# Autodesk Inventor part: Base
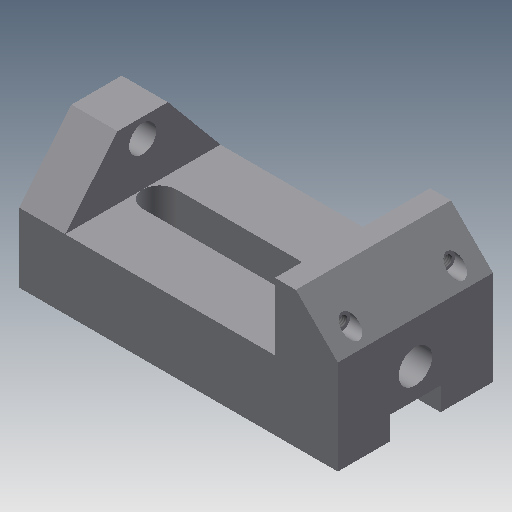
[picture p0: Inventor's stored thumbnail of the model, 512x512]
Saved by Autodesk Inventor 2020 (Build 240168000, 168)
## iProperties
Created: 2002-02
Part Number: Base
Document SubType Name: Modeling
Designer: ***
Density: 1 g/cm^3
Material: Generic
Appearance: Default
Control State: 0
Master: False
Checked Out: False
Shininess: 77.0
Length Units: 11269
Angle Units: 11279
Time Units: 11290
Mass Units: 11283
Length Display Precision: 3
Angle Display Precision: 2
Density: 0.0
Volumn: 0.0
Area: 0.0
PropertySet Name: Model Information
Author: ***
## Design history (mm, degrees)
sketch "Sketch2"
  geometry: L1 (-63.961, -4.254)-(-63.961, -37.254); L2 (-63.961, -37.254)-(88.039, -37.254); L3 (88.039, -37.254)-(88.039, 7.746); L4 (88.039, 7.746)-(68.039, 27.746); L5 (68.039, 27.746)-(58.039, 27.746); L6 (58.039, 27.746)-(58.039, -4.254); L7 (58.039, -4.254)-(-63.961, -4.254)
  constraints: 14 end point, 4 parallel, 1 perpendicular, 1 vertical
  dimensions: "d7" = 10 distance of L4.end L5.end; "d8" = 135 deg angle of L3 L4; "d9" = 33 distance of L1.start L1.end; "d10" = 152 distance of L1.end L2.end; "d11" = 65 distance between parallel lines of L5 L2; "d21" = 30 distance between parallel lines of L3 L6
extrude "Extrusion1" new body sketch "Sketch2" stored distance "d13" = 74; taper "d14" = 0 deg
sketch "Sketch3"
  geometry: L1 (0, 74)-(0, 0) reference; L2 (0, 0)-(-30, 25); L3 (-30, 25)-(-30, 49); L4 (-30, 49)-(0, 74); C1 r 6.5 at (-21, 37)
  constraints: 6 end point, 1 centre point, 1 equal length, 1 parallel
  dimensions: "d15" = 24 distance of L2.end L3.end; "d16" = 30 distance between parallel lines of L3 L1; "d17" = 13 diameter of C1; "d18" = 9 distance from line of L3 C1.centre
extrude "Extrusion2" join sketch "Sketch3" distance "d19" = 22; taper "d20" = 0 deg
sketch "Sketch4"
  geometry: L1 (0, 0)-(0, 74) reference; L2 (0, 0)-(45, 0) reference; C1 r 8 at (25, 37)
  constraints: 1 centre point
  dimensions: "d22" = 16 diameter of C1; "d23" = 25 distance from line of L1 C1.centre; "d24" = 37 distance from line of L2 C1.centre
extrude "Extrusion3" cut sketch "Sketch4" distance "d25" = 13; taper "d26" = 0 deg
sketch "Sketch5"
  geometry: L1 (45, 74)-(0, 74) reference; L2 (65, 0)-(65, 74) reference; 1 further point
  dimensions: "d27" = 12 distance from line of point (51, 62) L1; "d28" = 14 distance from line of L2 point (51, 62)
hole "Hole1" sketch "Sketch5" at (51, 62) diameter "d29" = 4.917; stored, may be unused: countersink angle "d33" = 82 deg, drill point angle "d35" = 0 deg; dims "d30" = 12, "d31" = 8, "d32" = 10, "d34" = 45
mirror "Mirror1"
sketch "Sketch6"
  geometry: L1 (100, 0)-(100, 74) reference; L2 (100, 74)-(0, 74) reference; L3 (14, 45)-(92, 45); L4 (92, 29)-(14, 29); A1 r 8 centre (92, 37) between (92, 29) and (92, 45); A2 r 8 centre (14, 37) between (14, 45) and (14, 29)
  constraints: 4 end point, 4 point on circle, 4 tangent, 2 centre point, 1 horizontal, 1 parallel
  dimensions: "d36" = 8 radius of A2; "d37" = 78 distance of L4.start L4.end; "d38" = 8 distance from line of L1 A1.centre; "d39" = 37 distance from line of L2 A2.centre
extrude "Extrusion4" cut sketch "Sketch6" extent not by distance; stored distance "d40" = 13; taper "d41" = 0 deg
sketch "Sketch7"
  geometry: L1 (45, 74)-(0, 74) reference; L2 (11, 49)-(0, 49); L3 (0, 49)-(0, 25); L4 (0, 25)-(11, 25); L5 (11, 25)-(11, 49); L6 (0, 0)-(45, 0) reference; L7 (0, 0)-(0, 74) reference
  constraints: 8 end point, 2 parallel, 1 collinear, 1 horizontal, 1 perpendicular
  dimensions: "d47" = 11 distance of L3.end L4.end; "d48" = 25 distance between parallel lines of L6 L4; "d49" = 24 distance of L2.end L3.end
extrude "Extrusion5" cut sketch "Sketch7" extent not by distance; stored distance "d45" = 13; taper "d46" = 0 deg
body "Solid1"
